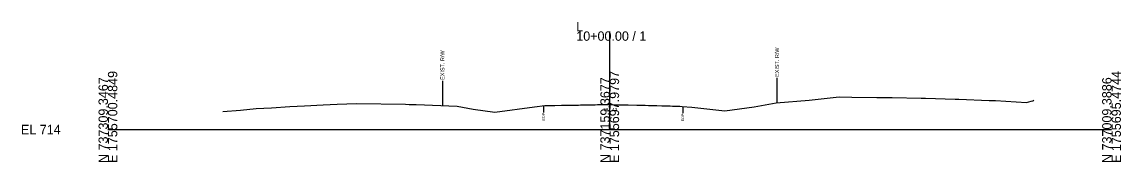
# Model space of a CAD drawing. Extents: x -26 to 4303, y -10 to 9577.
# Drawn here: x -25.7 to 302.8, y -9.7 to 32.1 of the extents above; entities that cross this region are included whole.
import ezdxf

# ---------------------------------------------------------------- set-up
doc = ezdxf.new("R2010")
doc.units = 0
for name, color, linetype in [('Default', 7, 'Continuous'), ('Old_Level_2', 7, 'Continuous'), ('Prop CMT Pvmt Course 1 CG', 7, 'Continuous'), ('Prop CMT Slope Grass', 7, 'Continuous'), ('Prop XS Ditch Standard Text', 7, 'Continuous'), ('Prop XS Earthwork Shape', 7, 'Continuous')]:
    doc.layers.add(name, color=color, linetype=linetype)

msp = doc.modelspace()

# ---------------------------------------------------------------- linework, layer by layer
at = {"layer": 'Old_Level_2'}
for p, q in [((150, 0), (150, 29.29)), ((150, 0), (150, 29.29)), ((0, 0), (150, 0)), ((150, 0), (300, 0)), ((0, 0), (150, 0)), ((150, 0), (300, 0))]:
    msp.add_line(p, q, dxfattribs=at)
at = {"layer": 'Prop CMT Slope Grass'}
msp.add_lwpolyline([(34.34, 5.36), (39.64, 5.82), (44.34, 6.26), (48.88, 6.49), (54.34, 6.87), (58.72, 7.09), (64.34, 7.4), (68.56, 7.57), (74.35, 7.74), (88.96, 7.52), (90.08, 7.51), (90.6, 7.51), (91.04, 7.48), (92.15, 7.44), (104.35, 6.93), (109.13, 6.12), (115.64, 5.19), (127.53, 6.78), (130.61, 7.16), (132.41, 7.2), (133.12, 7.2), (133.61, 7.2), (135.62, 7.23), (136.15, 7.25), (138.12, 7.3), (138.7, 7.31), (140.62, 7.31), (141.24, 7.33), (143.26, 7.37), (143.94, 7.38), (145.62, 7.41), (146.33, 7.42), (148.12, 7.45), (148.87, 7.44), (150, 7.43), (150.62, 7.42), (151.41, 7.41), (153.26, 7.39), (153.57, 7.37), (155.19, 7.36), (155.54, 7.36), (158.12, 7.27), (159.04, 7.25), (160.62, 7.23), (161.58, 7.2), (163.12, 7.15), (164.13, 7.14), (165.62, 7.11), (166.32, 7.09), (167.02, 7.07), (168.02, 7.04), (168.74, 7.02), (170.34, 6.95), (170.93, 6.94), (171.63, 6.92), (174.51, 6.7), (184.44, 5.53), (193.15, 6.81), (199.77, 7.99), (209.66, 8.76), (218.57, 9.76), (222.37, 9.65), (229.8, 9.57), (234.39, 9.55), (243.09, 9.37), (244.39, 9.32), (253.27, 9.05), (254.39, 9.02), (263.44, 8.67), (264.41, 8.66), (265.27, 8.66), (274.59, 8.04), (275.94, 8.48), (276.5, 8.53), (276.81, 8.72)], dxfattribs=at)
at = {"layer": 'Prop XS Ditch Standard Text'}
for p, q in [((100, 14.52), (100, 7.11)), ((200, 15.41), (200, 8.01)), ((130.22, 7.11), (130.22, 5.06)), ((171.85, 6.91), (171.85, 4.86))]:
    msp.add_line(p, q, dxfattribs=at)
at = {"layer": 'Prop XS Earthwork Shape'}
msp.add_line((0, 0), (0, 0), dxfattribs=at)

# ---------------------------------------------------------------- texts
at = {"layer": 'Default'}
msp.add_text('-', height=0.0001, dxfattribs=at).set_placement((0, 0))
at = {"layer": 'Old_Level_2'}
for s, p in [('L', (140, 29.29)), ('L', (140, 29.29)), ('10+00.00 / 1', (140, 26.49)), ('10+00.00 / 1', (140, 26.49)), ('EL 714', (-26, -1.4)), ('EL 714', (-26, -1.4))]:
    msp.add_text(s, height=2.8, dxfattribs=at).set_placement(p)
for s, p in [('E 1755700.4849', (2.8, -10)), ('E 1755700.4849', (2.8, -10)), ('E 1755697.9797', (152.8, -10)), ('E 1755697.9797', (152.8, -10)), ('E 1755695.4744', (302.8, -10)), ('E 1755695.4744', (302.8, -10)), ('N 737309.3467', (0, -10)), ('N 737309.3467', (0, -10)), ('N 737159.3677', (150, -10)), ('N 737159.3677', (150, -10)), ('N 737009.3886', (300, -10)), ('N 737009.3886', (300, -10))]:
    msp.add_text(s, height=2.8, rotation=90, dxfattribs=at).set_placement(p)
at = {"layer": 'Prop CMT Pvmt Course 1 CG'}
msp.add_text('721.43', height=1, dxfattribs=at).set_placement((148, 5.43))
at = {"layer": 'Prop XS Ditch Standard Text'}
for s, height, p in [('EXIST. R/W', 1.181, (100.59, 14.82)), ('EXIST. R/W', 1.181, (200.59, 15.71)), ('EOP', 0.787, (130.61, 2.66)), ('EOP', 0.787, (172.24, 2.46))]:
    msp.add_text(s, height=height, rotation=90, dxfattribs=at).set_placement(p)

doc.saveas('drawing.dxf')
